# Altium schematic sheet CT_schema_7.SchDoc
size 278 x 170 mm
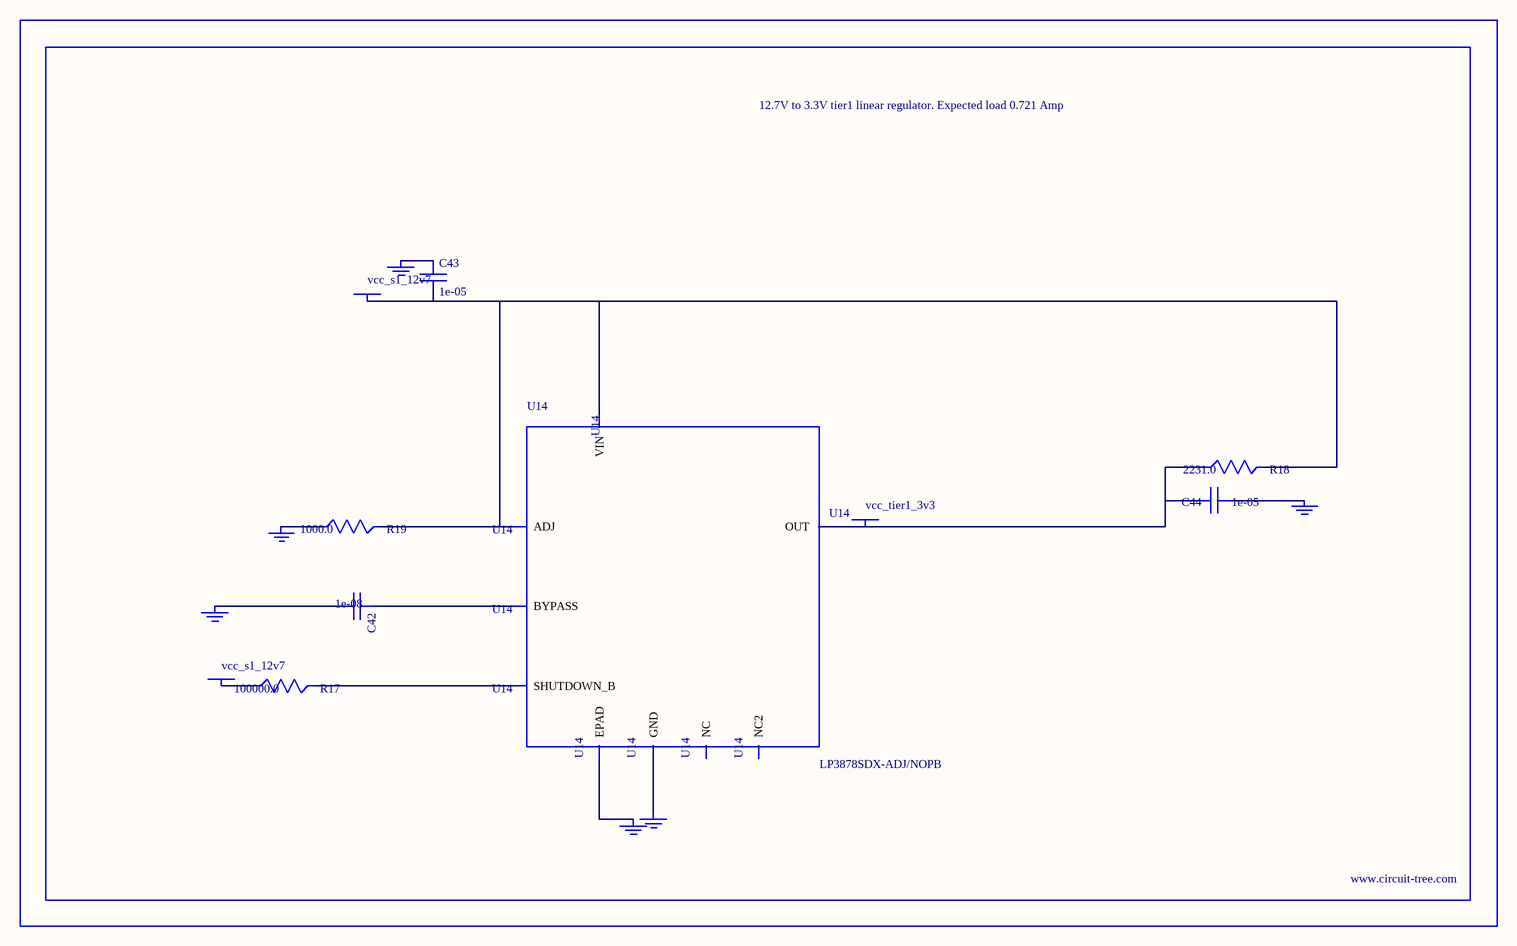
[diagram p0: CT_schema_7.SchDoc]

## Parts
BORDER6  (no value)
C42  1e-08  [C0402]
C43  1e-05  [C1210]
C44  1e-05  [C1210]
GND_INSTANCE_6_0  (no value)
GND_INSTANCE_6_1  (no value)
GND_INSTANCE_6_2  (no value)
GND_INSTANCE_6_3  (no value)
GND_INSTANCE_6_4  (no value)
GND_INSTANCE_6_5  (no value)
POWER_INSTANCE_6_0  vcc_s1_12v7
POWER_INSTANCE_6_1  vcc_s1_12v7
POWER_INSTANCE_6_2  vcc_tier1_3v3
R17  100000.0  [R0603]
R18  2231.0  [R0603]
R19  1000.0  [R0603]
U14  LP3878SDX-ADJ/NOPB  [WSON-8]

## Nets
NetC42_1: C42.1 U14.1(BYPASS)
NetC42_2: C42.2 GND_INSTANCE_6_0.0(GND)
NetC43_1: C43.1 GND_INSTANCE_6_1.0(GND)
NetC43_2: C43.2 POWER_INSTANCE_6_0.0(PWR) R18.2 R19.2 U14.4(VIN) U14.6(ADJ)
NetC44_1: C44.1 GND_INSTANCE_6_2.0(GND)
NetC44_2: C44.2 POWER_INSTANCE_6_2.0(PWR) R18.1 U14.5(OUT)
NetGND_INSTANCE_6_3_0: GND_INSTANCE_6_3.0(GND) R19.1
NetGND_INSTANCE_6_4_0: GND_INSTANCE_6_4.0(GND) U14.PAD(EPAD)
NetGND_INSTANCE_6_5_0: GND_INSTANCE_6_5.0(GND) U14.3(GND)
NetPOWER_INSTANCE_6_1_0: POWER_INSTANCE_6_1.0(PWR) R17.1
NetR17_2: R17.2 U14.8(SHUTDOWN_B)

Not connected (* = marked no-connect by the designer): U14 2(NC) 7(NC2)

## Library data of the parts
BORDER6 = BORDER_PAGE6
C42 = C0402C103K3RAC
C43 = C1210C106K5PACTU
C44 = GRM32DR61E106MA12L
GND_INSTANCE_6_0-GND_INSTANCE_6_5 = GND
POWER_INSTANCE_6_0-POWER_INSTANCE_6_2 = PWR
R17 = RC0603JR-07100KL
R18 = R18
R19 = RC0603JR-071KL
